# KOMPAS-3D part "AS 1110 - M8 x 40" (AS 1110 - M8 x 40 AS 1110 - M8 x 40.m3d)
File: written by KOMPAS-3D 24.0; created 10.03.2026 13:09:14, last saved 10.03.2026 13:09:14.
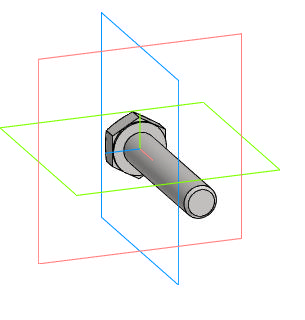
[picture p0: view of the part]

Document properties: Автор: R2D2; Полное имя файла: E:\Работа\Зайцев\BV3232P(4pc)-FP-3WL-F-ISO-H Кран шаровой DN.ru Ду15-100 Ру16\DN80\исходные материалы\AS 1110 - M8 x 40 AS 1110 - M8 x 40.m3d

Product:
- Body: Solid1  | qty 1
- Part/product: AS 1110 - M8 x 40
    Комментарий: Болты и винты   шестигранные точные   метрические ISO
    additional columns: Сталь, мягкая

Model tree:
1. Solid1  (labels: Solid1)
